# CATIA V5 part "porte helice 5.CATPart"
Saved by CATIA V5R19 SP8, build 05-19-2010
Part number: porte helice 5
Bounding box of the stored display mesh (mm): x -20 to 20, y -50 to 180, z -20 to 20
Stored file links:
  G:\EU_thinkMotion\CFAO_2010\MMS_groupe2\MMS_groupe2\A reprendre\splanchenault\Planchenault\porte helice 5.CATPart
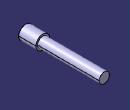
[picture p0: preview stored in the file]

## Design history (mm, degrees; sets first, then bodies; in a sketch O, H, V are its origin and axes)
Body1 (main body)
  Sketch1 on zx-plane, origin (0, 0, 0), H (-1, 0, 0), V (0, 0, 1)
    circle A1 centre (0, 0) radius 15
    radius A1 = 15
  Pad1: profile Sketch1, direction (0, 1, 0), length 180
  Sketch2 on start face of Pad1, origin (0, 0, 0), H (1, 0, 0), V (0, 0, 1)
    circle A1 centre (0, 0) radius 20
    radius A1 = 20
  Pad2: profile Sketch2, direction (0, -1, 0), length 50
